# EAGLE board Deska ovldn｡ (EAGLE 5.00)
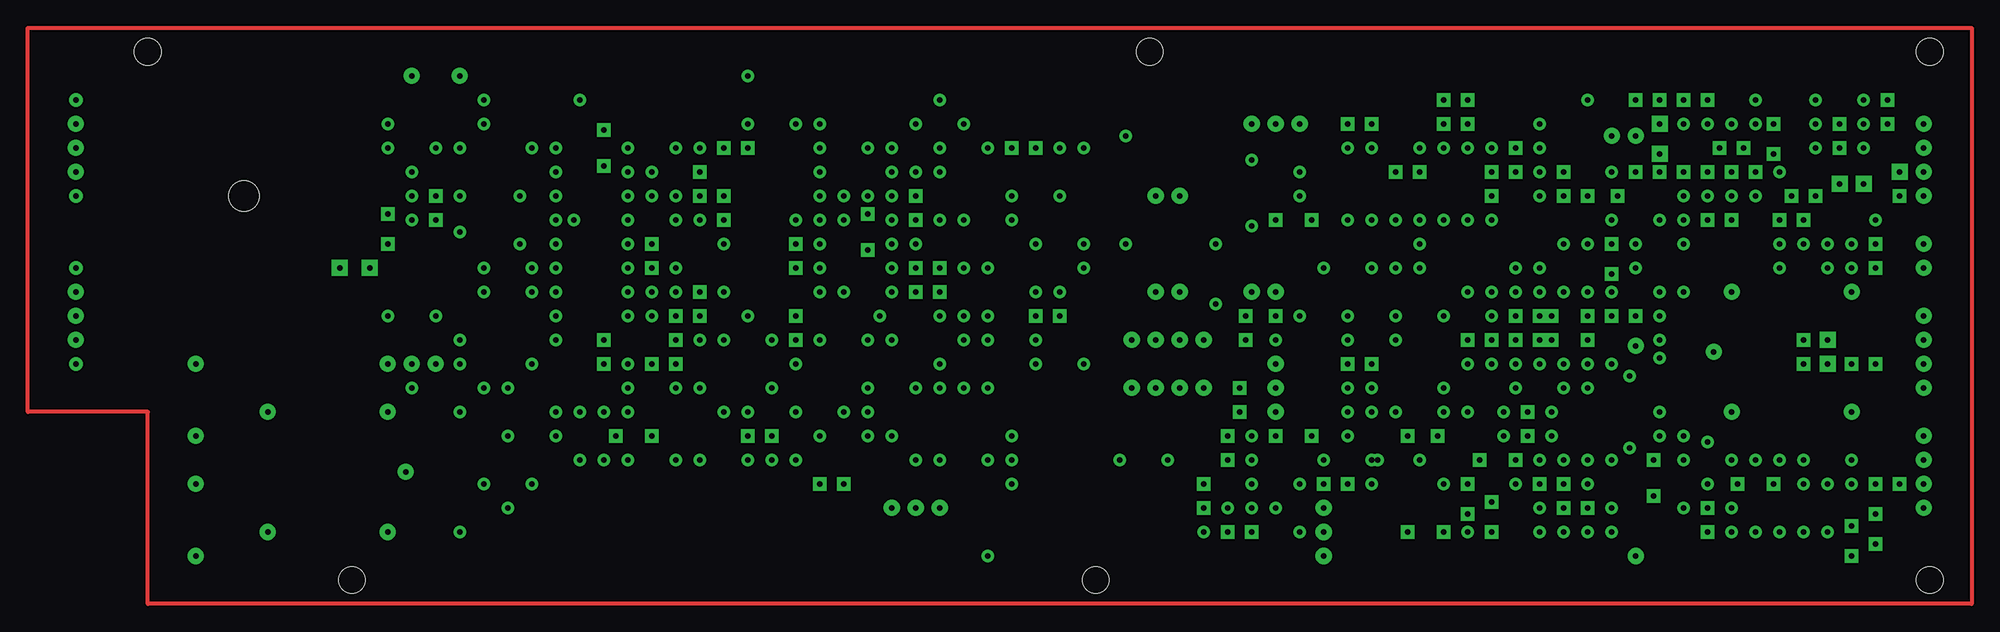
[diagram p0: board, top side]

No outline drawn. Coordinates in mm, seen from the top.
Copper layers (1*16): Top 0.035mm / dielectric 1.5mm / Bottom 0.035mm
Design rules "default": minimum track width 10mil, minimum drill 0.6mm, track to track 8mil, track to pad 8mil, pad to pad 8mil, via to via 8mil, smd to smd 8mil, copper to edge 40mil, drill to drill 8mil, minimum pad ring 10mil, minimum via ring 8mil, stop-mask expansion 4mil, vias tented up to drill 0mil, thermal gap 10mil
Holes 2.8 mm at 98.75,2.5 21.25,2.5 0,57.5 104.38,57.5 185.62,2.5 185.62,57.5
Holes 3.2 mm at 10,42.5

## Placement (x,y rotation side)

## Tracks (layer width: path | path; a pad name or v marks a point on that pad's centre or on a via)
S$1
  Top 0.406: 0,0 0,20 -12.5,20 -12.5,60 190,60 190,0 0,0
S$2  (via drill 0.6 pad 1.68)
  other vias: 5,5
S$3  (via drill 0.6 pad 1.68)
  other vias: 5,12.5
S$4  (via drill 0.6 pad 1.68)
  other vias: 5,17.5
S$5  (via drill 0.6 pad 1.68)
  other vias: 5,25
S$6  (via drill 0.6 pad 1.68)
  other vias: -7.5,50
S$7  (via drill 0.6 pad 1.68)
  other vias: -7.5,45
S$8  (via drill 0.6 pad 1.68)
  other vias: -7.5,27.5
S$9  (via drill 0.6 pad 1.68)
  other vias: -7.5,32.5
S$10  (via drill 0.6 pad 1.68)
  other vias: 12.5,7.5
S$11  (via drill 0.6 pad 1.68)
  other vias: 12.5,20
S$12  (via drill 0.6 pad 1.68)
  other vias: 25,20
S$13  (via drill 0.6 pad 1.68)
  other vias: 25,7.5
S$14  (via drill 0.6 pad 1.68)
  other vias: 26.88,13.75
S$15  (via drill 0.6 pad 1.68)
  other vias: 25,25
S$16  (via drill 0.6 pad 1.27)
  other vias: 25,30
S$17  (via drill 0.6 pad 1.68)
  other vias: 20,35
S$18  (via drill 0.6 pad 1.27)
  other vias: 27.5,40
S$19  (via drill 0.6 pad 1.27)
  other vias: 27.5,42.5
S$20  (via drill 0.6 pad 1.27)
  other vias: 27.5,45
S$21  (via drill 0.6 pad 1.27)
  other vias: 25,47.5
S$22  (via drill 0.6 pad 1.27)
  other vias: 25,50
S$23  (via drill 0.6 pad 1.68)
  other vias: 27.5,55
S$24  (via drill 0.6 pad 1.68)
  other vias: 32.5,55
S$25  (via drill 0.6 pad 1.27)
  other vias: 35,52.5
S$26  (via drill 0.6 pad 1.27)
  other vias: 35,50
S$27  (via drill 0.6 pad 1.27)
  other vias: 32.5,47.5
S$28  (via drill 0.6 pad 1.27)
  other vias: 30,47.5
S$29  (via drill 0.6 pad 1.27)
  other vias: 32.5,42.5
S$30  (via drill 0.6 pad 1.27)
  other vias: 32.5,38.75
S$31  (via drill 0.6 pad 1.27)
  other vias: 38.75,42.5
S$32  (via drill 0.6 pad 1.27)
  other vias: 38.75,37.5
S$33  (via drill 0.6 pad 1.27)
  other vias: 40,47.5
S$34  (via drill 0.6 pad 1.27)
  other vias: 42.5,47.5
S$35  (via drill 0.6 pad 1.27)
  other vias: 42.5,45
S$36  (via drill 0.6 pad 1.27)
  other vias: 42.5,42.5
S$37  (via drill 0.6 pad 1.27)
  other vias: 42.5,40
S$38  (via drill 0.6 pad 1.27)
  other vias: 42.5,37.5
S$39  (via drill 0.6 pad 1.27)
  other vias: 42.5,35
S$40  (via drill 0.6 pad 1.27)
  other vias: 42.5,32.5
S$41  (via drill 0.6 pad 1.27)
  other vias: 42.5,30
S$42  (via drill 0.6 pad 1.27)
  other vias: 42.5,27.5
S$43  (via drill 0.6 pad 1.27)
  other vias: 50,47.5
S$44  (via drill 0.6 pad 1.27)
  other vias: 50,45
S$45  (via drill 0.6 pad 1.27)
  other vias: 50,42.5
S$46  (via drill 0.6 pad 1.27)
  other vias: 50,40
S$47  (via drill 0.6 pad 1.27)
  other vias: 50,37.5
S$48  (via drill 0.6 pad 1.27)
  other vias: 50,35
S$49  (via drill 0.6 pad 1.27)
  other vias: 50,32.5
S$50  (via drill 0.6 pad 1.27)
  other vias: 50,30
S$51  (via drill 0.6 pad 1.27)
  other vias: 55,47.5
S$52  (via drill 0.6 pad 1.27)
  other vias: 57.5,47.5
S$53  (via drill 0.6 pad 1.27)
  other vias: 52.5,45
S$54  (via drill 0.6 pad 1.27)
  other vias: 52.5,42.5
S$55  (via drill 0.6 pad 1.27)
  other vias: 55,42.5
S$56  (via drill 0.6 pad 1.27)
  other vias: 55,40
S$57  (via drill 0.6 pad 1.27)
  other vias: 57.5,40
S$58  (via drill 0.6 pad 1.27)
  other vias: 60,37.5
S$59  (via drill 0.6 pad 1.27)
  other vias: 55,35
S$60  (via drill 0.6 pad 1.27)
  other vias: 55,32.5
S$61  (via drill 0.6 pad 1.27)
  other vias: 52.5,32.5
S$62  (via drill 0.6 pad 1.27)
  other vias: 52.5,30
S$63  (via drill 0.6 pad 1.27)
  other vias: 60,32.5
S$64  (via drill 0.6 pad 1.27)
  other vias: 60,27.5
S$65  (via drill 0.6 pad 1.27)
  other vias: 57.5,27.5
S$66  (via drill 0.6 pad 1.27)
  other vias: 57.5,22.5
S$67  (via drill 0.6 pad 1.27)
  other vias: 55,22.5
S$68  (via drill 0.6 pad 1.27)
  other vias: 50,25
S$69  (via drill 0.6 pad 1.27)
  other vias: 50,22.5
S$70  (via drill 0.6 pad 1.27)
  other vias: 50,20
S$71  (via drill 0.6 pad 1.27)
  other vias: 47.5,20
S$72  (via drill 0.6 pad 1.27)
  other vias: 45,20
S$73  (via drill 0.6 pad 1.27)
  other vias: 42.5,20
S$74  (via drill 0.6 pad 1.27)
  other vias: 42.5,17.5
S$75  (via drill 0.6 pad 1.27)
  other vias: 45,15
S$76  (via drill 0.6 pad 1.27)
  other vias: 47.5,15
S$77  (via drill 0.6 pad 1.27)
  other vias: 50,15
S$78  (via drill 0.6 pad 1.27)
  other vias: 37.5,17.5
S$79  (via drill 0.6 pad 1.27)
  other vias: 37.5,10
S$80  (via drill 0.6 pad 1.27)
  other vias: 40,12.5
S$81  (via drill 0.6 pad 1.27)
  other vias: 35,12.5
S$82  (via drill 0.6 pad 1.27)
  other vias: 32.5,7.5
S$83  (via drill 0.6 pad 1.27)
  other vias: 32.5,20
S$84  (via drill 0.6 pad 1.27)
  other vias: 35,22.5
S$85  (via drill 0.6 pad 1.27)
  other vias: 37.5,22.5
S$86  (via drill 0.6 pad 1.27)
  other vias: 40,25
S$87  (via drill 0.6 pad 1.27)
  other vias: 32.5,25
S$88  (via drill 0.6 pad 1.27)
  other vias: 32.5,27.5
S$89  (via drill 0.6 pad 1.68)
  other vias: 30,25
S$90  (via drill 0.6 pad 1.27)
  other vias: 27.5,22.5
S$91  (via drill 0.6 pad 1.27)
  other vias: 72.5,42.5
S$92  (via drill 0.6 pad 1.27)
  other vias: 30,30
S$93  (via drill 0.6 pad 1.68)
  other vias: 23.12,35
S$94  (via drill 0.6 pad 1.27)
  other vias: 35,35
S$95  (via drill 0.6 pad 1.27)
  other vias: 35,32.5
S$96  (via drill 0.6 pad 1.27)
  other vias: 40,32.5
S$97  (via drill 0.6 pad 1.27)
  other vias: 40,35
S$98  (via drill 0.6 pad 1.27)
  other vias: 45,52.5
S$99  (via drill 0.6 pad 1.27)
  other vias: 62.5,30
S$100  (via drill 0.6 pad 1.27)
  other vias: 65,27.5
S$101  (via drill 0.6 pad 1.27)
  other vias: 67.5,25
S$102  (via drill 0.6 pad 1.27)
  other vias: 70,27.5
S$103  (via drill 0.6 pad 1.27)
  other vias: 70,47.5
S$104  (via drill 0.6 pad 1.27)
  other vias: 70,45
S$105  (via drill 0.6 pad 1.27)
  other vias: 70,42.5
S$106  (via drill 0.6 pad 1.27)
  other vias: 70,40
S$107  (via drill 0.6 pad 1.27)
  other vias: 70,37.5
S$108  (via drill 0.6 pad 1.27)
  other vias: 70,35
S$109  (via drill 0.6 pad 1.27)
  other vias: 70,32.5
S$110  (via drill 0.6 pad 1.27)
  other vias: 72.5,32.5
S$111  (via drill 0.6 pad 1.27)
  other vias: 77.5,32.5
S$112  (via drill 0.6 pad 1.27)
  other vias: 77.5,35
S$113  (via drill 0.6 pad 1.27)
  other vias: 77.5,37.5
S$114  (via drill 0.6 pad 1.27)
  other vias: 77.5,40
S$115  (via drill 0.6 pad 1.27)
  other vias: 77.5,42.5
S$116  (via drill 0.6 pad 1.27)
  other vias: 77.5,45
S$117  (via drill 0.6 pad 1.27)
  other vias: 77.5,47.5
S$118  (via drill 0.6 pad 1.27)
  other vias: 80,50
S$119  (via drill 0.6 pad 1.27)
  other vias: 80,45
S$120  (via drill 0.6 pad 1.27)
  other vias: 82.5,45
S$121  (via drill 0.6 pad 1.27)
  other vias: 82.5,47.5
S$122  (via drill 0.6 pad 1.27)
  other vias: 82.5,40
S$123  (via drill 0.6 pad 1.27)
  other vias: 82.5,52.5
S$124  (via drill 0.6 pad 1.27)
  other vias: 85,50
S$125  (via drill 0.6 pad 1.27)
  other vias: 85,40
S$126  (via drill 0.6 pad 1.27)
  other vias: 80,37.5
S$127  (via drill 0.6 pad 1.27)
  other vias: 85,35
S$128  (via drill 0.6 pad 1.27)
  other vias: 87.5,35
S$129  (via drill 0.6 pad 1.27)
  other vias: 85,30
S$130  (via drill 0.6 pad 1.27)
  other vias: 87.5,30
S$131  (via drill 0.6 pad 1.27)
  other vias: 85,27.5
S$132  (via drill 0.6 pad 1.27)
  other vias: 87.5,27.5
S$133  (via drill 0.6 pad 1.27)
  other vias: 65,22.5
S$134  (via drill 0.6 pad 1.27)
  other vias: 62.5,20
S$135  (via drill 0.6 pad 1.27)
  other vias: 62.5,15
S$136  (via drill 0.6 pad 1.27)
  other vias: 65,15
S$137  (via drill 0.6 pad 1.27)
  other vias: 67.5,15
S$138  (via drill 0.6 pad 1.27)
  other vias: 67.5,20
S$139  (via drill 0.6 pad 1.27)
  other vias: 70,17.5
S$140  (via drill 0.6 pad 1.27)
  other vias: 72.5,20
S$141  (via drill 0.6 pad 1.27)
  other vias: 60,20
S$142  (via drill 0.6 pad 1.27)
  other vias: 57.5,15
S$143  (via drill 0.6 pad 1.27)
  other vias: 55,15
S$144  (via drill 0.6 pad 1.27)
  other vias: 75,27.5
S$145  (via drill 0.6 pad 1.27)
  other vias: 76.25,30
S$146  (via drill 0.6 pad 1.27)
  other vias: 67.5,40
S$147  (via drill 0.6 pad 1.27)
  other vias: 70,50
S$148  (via drill 0.6 pad 1.27)
  other vias: 67.5,50
S$149  (via drill 0.6 pad 1.27)
  other vias: 62.5,50
S$150  (via drill 0.6 pad 1.27)
  other vias: 62.5,55
S$151  (via drill 0.6 pad 1.42)
  other vias: 30,42.5
S$152  (via drill 0.6 pad 1.42)
  other vias: 30,40
S$153  (via drill 0.6 pad 1.42)
  other vias: 25,40.62
S$154  (via drill 0.6 pad 1.42)
  other vias: 25,37.5
S$155  (via drill 0.6 pad 1.42)
  other vias: 47.5,45.62
S$156  (via drill 0.6 pad 1.42)
  other vias: 47.5,49.38
S$157  (via drill 0.6 pad 1.42)
  other vias: 47.5,27.5
S$158  (via drill 0.6 pad 1.42)
  other vias: 47.5,25
S$159  (via drill 0.6 pad 1.42)
  other vias: 52.5,25
S$160  (via drill 0.6 pad 1.42)
  other vias: 55,25
S$161  (via drill 0.6 pad 1.42)
  other vias: 55,27.5
S$162  (via drill 0.6 pad 1.42)
  other vias: 55,30
S$163  (via drill 0.6 pad 1.42)
  other vias: 57.5,30
S$164  (via drill 0.6 pad 1.42)
  other vias: 57.5,32.5
S$165  (via drill 0.6 pad 1.42)
  other vias: 52.5,35
S$166  (via drill 0.6 pad 1.42)
  other vias: 52.5,37.5
S$167  (via drill 0.6 pad 1.42)
  other vias: 60,47.5
S$168  (via drill 0.6 pad 1.42)
  other vias: 62.5,47.5
S$169  (via drill 0.6 pad 1.42)
  other vias: 57.5,45
S$170  (via drill 0.6 pad 1.42)
  other vias: 57.5,42.5
S$171  (via drill 0.6 pad 1.42)
  other vias: 60,42.5
S$172  (via drill 0.6 pad 1.42)
  other vias: 60,40
S$173  (via drill 0.6 pad 1.42)
  other vias: 67.5,37.5
S$174  (via drill 0.6 pad 1.42)
  other vias: 67.5,35
S$175  (via drill 0.6 pad 1.42)
  other vias: 67.5,30
S$176  (via drill 0.6 pad 1.42)
  other vias: 67.5,27.5
S$177  (via drill 0.6 pad 1.42)
  other vias: 62.5,17.5
S$178  (via drill 0.6 pad 1.42)
  other vias: 65,17.5
S$179  (via drill 0.6 pad 1.42)
  other vias: 70,12.5
S$180  (via drill 0.6 pad 1.42)
  other vias: 72.5,12.5
S$181  (via drill 0.6 pad 1.42)
  other vias: 52.5,17.5
S$182  (via drill 0.6 pad 1.42)
  other vias: 48.75,17.5
S$183  (via drill 0.6 pad 1.42)
  other vias: 80,42.5
S$184  (via drill 0.6 pad 1.42)
  other vias: 80,40
S$185  (via drill 0.6 pad 1.42)
  other vias: 80,35
S$186  (via drill 0.6 pad 1.42)
  other vias: 80,32.5
S$187  (via drill 0.6 pad 1.42)
  other vias: 82.5,32.5
S$188  (via drill 0.6 pad 1.42)
  other vias: 82.5,35
S$189  (via drill 0.6 pad 1.42)
  other vias: -7.5,52.5
S$190  (via drill 0.6 pad 1.42)
  other vias: -7.5,42.5
S$191  (via drill 0.6 pad 1.42)
  other vias: -7.5,35
S$192  (via drill 0.6 pad 1.42)
  other vias: -7.5,25
S$193  (via drill 0.6 pad 1.27)
  other vias: 75,22.5
S$194  (via drill 0.6 pad 1.27)
  other vias: 75,20
S$195  (via drill 0.6 pad 1.27)
  other vias: 75,17.5
S$196  (via drill 0.6 pad 1.27)
  other vias: 77.5,17.5
S$197  (via drill 0.6 pad 1.27)
  other vias: 80,22.5
S$198  (via drill 0.6 pad 1.27)
  other vias: 82.5,22.5
S$199  (via drill 0.6 pad 1.27)
  other vias: 82.5,15
S$200  (via drill 0.6 pad 1.27)
  other vias: 80,15
S$201  (via drill 0.6 pad 1.68)
  other vias: 80,10 77.5,10
S$202  (via drill 0.6 pad 1.68)
  other vias: 82.5,10
S$203  (via drill 0.6 pad 1.27)
  other vias: 85,22.5
S$204  (via drill 0.6 pad 1.27)
  other vias: 87.5,22.5
S$205  (via drill 0.6 pad 1.27)
  other vias: 44.38,40
S$206  (via drill 0.6 pad 1.27)
  other vias: 72.5,40
S$207  (via drill 0.6 pad 1.27)
  other vias: 75,42.5
S$208  (via drill 0.6 pad 1.27)
  other vias: 75,47.5
S$209  (via drill 0.6 pad 1.27)
  other vias: 77.5,27.5
S$210  (via drill 0.6 pad 1.27)
  other vias: 82.5,30
S$211  (via drill 0.6 pad 1.27)
  other vias: 82.5,25
S$212  (via drill 0.6 pad 1.27)
  other vias: 90,40
S$213  (via drill 0.6 pad 1.27)
  other vias: 90,42.5
S$214  (via drill 0.6 pad 1.27)
  other vias: 92.5,37.5
S$215  (via drill 0.6 pad 1.27)
  other vias: 92.5,32.5
S$216  (via drill 0.6 pad 1.27)
  other vias: 92.5,27.5
S$217  (via drill 0.6 pad 1.27)
  other vias: 92.5,25
S$218  (via drill 0.6 pad 1.27)
  other vias: 97.5,25
S$219  (via drill 0.6 pad 1.27)
  other vias: 87.5,15
S$220  (via drill 0.6 pad 1.27)
  other vias: 90,17.5
S$221  (via drill 0.6 pad 1.27)
  other vias: 90,15
S$222  (via drill 0.6 pad 1.27)
  other vias: 90,12.5
S$223  (via drill 0.6 pad 1.27)
  other vias: 87.5,5
S$224  (via drill 0.6 pad 1.27)
  other vias: 87.5,47.5
S$225  (via drill 0.6 pad 1.27)
  other vias: 95,47.5
S$226  (via drill 0.6 pad 1.27)
  other vias: 97.5,47.5
S$227  (via drill 0.6 pad 1.27)
  other vias: 101.88,48.75
S$228  (via drill 0.6 pad 1.27)
  other vias: 97.5,37.5
S$229  (via drill 0.6 pad 1.27)
  other vias: 97.5,35
S$230  (via drill 0.6 pad 1.27)
  other vias: 95,32.5
S$231  (via drill 0.6 pad 1.27)
  other vias: 95,42.5
S$232  (via drill 0.6 pad 1.27)
  other vias: 101.88,37.5
S$233  (via drill 0.6 pad 1.27)
  other vias: 111.25,37.5
S$234  (via drill 0.6 pad 1.68)
  other vias: 105,42.5
S$235  (via drill 0.6 pad 1.68)
  other vias: 107.5,42.5
S$236  (via drill 0.6 pad 1.68)
  other vias: 107.5,32.5
S$237  (via drill 0.6 pad 1.68)
  other vias: 105,32.5
S$238  (via drill 0.6 pad 1.68)
  other vias: 102.5,27.5
S$239  (via drill 0.6 pad 1.68)
  other vias: -7.5,47.5
S$240  (via drill 0.6 pad 1.68)
  other vias: -7.5,30
S$241  (via drill 0.6 pad 1.68)
  other vias: 105,27.5
S$242  (via drill 0.6 pad 1.68)
  other vias: 107.5,27.5
S$243  (via drill 0.6 pad 1.68)
  other vias: 110,27.5
S$244  (via drill 0.6 pad 1.68)
  other vias: 110,22.5
S$245  (via drill 0.6 pad 1.68)
  other vias: 102.5,22.5
S$246  (via drill 0.6 pad 1.68)
  other vias: 105,22.5
S$247  (via drill 0.6 pad 1.68)
  other vias: 107.5,22.5
S$248  (via drill 0.6 pad 1.27)
  other vias: 106.25,15
S$249  (via drill 0.6 pad 1.27)
  other vias: 101.25,15
S$250  (via drill 0.6 pad 1.68)
  other vias: 115,50
S$251  (via drill 0.6 pad 1.68)
  other vias: 120,50
S$252  (via drill 0.6 pad 1.68)
  other vias: 117.5,50
S$253  (via drill 0.6 pad 1.27)
  other vias: 115,46.25
S$254  (via drill 0.6 pad 1.27)
  other vias: 115,39.38
S$255  (via drill 0.6 pad 1.27)
  other vias: 120,45
S$256  (via drill 0.6 pad 1.27)
  other vias: 120,42.5
S$257  (via drill 0.6 pad 1.27)
  other vias: 125,47.5
S$258  (via drill 0.6 pad 1.27)
  other vias: 127.5,47.5
S$259  (via drill 0.6 pad 1.27)
  other vias: 125,40
S$260  (via drill 0.6 pad 1.27)
  other vias: 127.5,40
S$261  (via drill 0.6 pad 1.27)
  other vias: 130,40
S$262  (via drill 0.6 pad 1.27)
  other vias: 132.5,40
S$263  (via drill 0.6 pad 1.27)
  other vias: 135,40
S$264  (via drill 0.6 pad 1.27)
  other vias: 137.5,40
S$265  (via drill 0.6 pad 1.27)
  other vias: 140,40
S$266  (via drill 0.6 pad 1.27)
  other vias: 140,47.5
S$267  (via drill 0.6 pad 1.27)
  other vias: 137.5,47.5
S$268  (via drill 0.6 pad 1.27)
  other vias: 135,47.5
S$269  (via drill 0.6 pad 1.27)
  other vias: 132.5,47.5
S$270  (via drill 0.6 pad 1.27)
  other vias: 145,47.5
S$271  (via drill 0.6 pad 1.27)
  other vias: 145,50
S$272  (via drill 0.6 pad 1.27)
  other vias: 145,45
S$273  (via drill 0.6 pad 1.27)
  other vias: 145,42.5
S$274  (via drill 0.6 pad 1.27)
  other vias: 132.5,37.5
S$275  (via drill 0.6 pad 1.27)
  other vias: 147.5,37.5
S$276  (via drill 0.6 pad 1.27)
  other vias: 132.5,35
S$277  (via drill 0.6 pad 1.27)
  other vias: 130,35
S$278  (via drill 0.6 pad 1.27)
  other vias: 127.5,35
S$279  (via drill 0.6 pad 1.27)
  other vias: 122.5,35
S$280  (via drill 0.6 pad 1.68)
  other vias: 115,32.5
S$281  (via drill 0.6 pad 1.68)
  other vias: 117.5,32.5
S$282  (via drill 0.6 pad 1.27)
  other vias: 117.5,27.5
S$283  (via drill 0.6 pad 1.27)
  other vias: 120,30
S$284  (via drill 0.6 pad 1.27)
  other vias: 125,30
S$285  (via drill 0.6 pad 1.27)
  other vias: 125,27.5
S$286  (via drill 0.6 pad 1.27)
  other vias: 130,30
S$287  (via drill 0.6 pad 1.27)
  other vias: 130,27.5
S$288  (via drill 0.6 pad 1.27)
  other vias: 125,22.5
S$289  (via drill 0.6 pad 1.27)
  other vias: 127.5,22.5
S$290  (via drill 0.6 pad 1.27)
  other vias: 127.5,20
S$291  (via drill 0.6 pad 1.27)
  other vias: 125,20
S$292  (via drill 0.6 pad 1.27)
  other vias: 130,20
S$293  (via drill 0.6 pad 1.27)
  other vias: 125,17.5
S$294  (via drill 0.6 pad 1.27)
  other vias: 127.5,15
S$295  (via drill 0.6 pad 1.27)
  other vias: 122.5,15
S$296  (via drill 0.6 pad 1.27)
  other vias: 120,12.5
S$297  (via drill 0.6 pad 1.27)
  other vias: 127.5,12.5
S$298  (via drill 0.6 pad 1.68)
  other vias: 122.5,10
S$299  (via drill 0.6 pad 1.68)
  other vias: 122.5,7.5
S$300  (via drill 0.6 pad 1.68)
  other vias: 122.5,5
S$301  (via drill 0.6 pad 1.68)
  other vias: 117.5,25
S$302  (via drill 0.6 pad 1.68)
  other vias: 117.5,22.5
S$303  (via drill 0.6 pad 1.68)
  other vias: 117.5,20
S$304  (via drill 0.6 pad 1.27)
  other vias: 115,17.5
S$305  (via drill 0.6 pad 1.27)
  other vias: 115,15
S$306  (via drill 0.6 pad 1.27)
  other vias: 115,12.5
S$307  (via drill 0.6 pad 1.27)
  other vias: 115,10
S$308  (via drill 0.6 pad 1.27)
  other vias: 117.5,10
S$309  (via drill 0.6 pad 1.27)
  other vias: 112.5,10
S$310  (via drill 0.6 pad 1.27)
  other vias: 110,7.5
S$311  (via drill 0.6 pad 1.27)
  other vias: 128.12,15
S$312  (via drill 0.6 pad 1.27)
  other vias: 132.5,15
S$313  (via drill 0.6 pad 1.27)
  other vias: 135,12.5 135,12.5
S$314  (via drill 0.6 pad 1.27)
  other vias: 135,20
S$315  (via drill 0.6 pad 1.27)
  other vias: 137.5,20
S$316  (via drill 0.6 pad 1.27)
  other vias: 135,22.5
S$317  (via drill 0.6 pad 1.27)
  other vias: 137.5,7.5
S$318  (via drill 0.6 pad 1.27)
  other vias: 145,7.5
S$319  (via drill 0.6 pad 1.27)
  other vias: 147.5,7.5
S$320  (via drill 0.6 pad 1.27)
  other vias: 150,7.5
S$321  (via drill 0.6 pad 1.27)
  other vias: 152.5,7.5
S$322  (via drill 0.6 pad 1.42)
  other vias: 90,47.5
S$323  (via drill 0.6 pad 1.42)
  other vias: 92.5,47.5
S$324  (via drill 0.6 pad 1.42)
  other vias: 92.5,30
S$325  (via drill 0.6 pad 1.42)
  other vias: 95,30
S$326  (via drill 0.6 pad 1.42)
  other vias: 117.5,40
S$327  (via drill 0.6 pad 1.42)
  other vias: 121.25,40
S$328  (via drill 0.6 pad 1.42)
  other vias: 125,50
S$329  (via drill 0.6 pad 1.42)
  other vias: 127.5,50
S$330  (via drill 0.6 pad 1.42)
  other vias: 135,50
S$331  (via drill 0.6 pad 1.42)
  other vias: 135,52.5
S$332  (via drill 0.6 pad 1.42)
  other vias: 137.5,52.5
S$333  (via drill 0.6 pad 1.42)
  other vias: 137.5,50
S$334  (via drill 0.6 pad 1.42)
  other vias: 142.5,47.5
S$335  (via drill 0.6 pad 1.42)
  other vias: 142.5,45
S$336  (via drill 0.6 pad 1.42)
  other vias: 140,45
S$337  (via drill 0.6 pad 1.42)
  other vias: 140,42.5
S$338  (via drill 0.6 pad 1.42)
  other vias: 147.5,45
S$339  (via drill 0.6 pad 1.42)
  other vias: 147.5,42.5
S$340  (via drill 0.6 pad 1.42)
  other vias: 132.5,45
S$341  (via drill 0.6 pad 1.42)
  other vias: 130,45
S$342  (via drill 0.6 pad 1.27)
  other vias: 111.25,31.25
S$343  (via drill 0.6 pad 1.42)
  other vias: 114.38,30
S$344  (via drill 0.6 pad 1.42)
  other vias: 117.5,30
S$345  (via drill 0.6 pad 1.42)
  other vias: 125,25
S$346  (via drill 0.6 pad 1.42)
  other vias: 127.5,25
S$347  (via drill 0.6 pad 1.42)
  other vias: 122.5,12.5
S$348  (via drill 0.6 pad 1.42)
  other vias: 125,12.5
S$349  (via drill 0.6 pad 1.42)
  other vias: 115,7.5
S$350  (via drill 0.6 pad 1.42)
  other vias: 112.5,7.5
S$351  (via drill 0.6 pad 1.42)
  other vias: 110,10
S$352  (via drill 0.6 pad 1.42)
  other vias: 110,12.5
S$353  (via drill 0.6 pad 1.42)
  other vias: 112.5,15
S$354  (via drill 0.6 pad 1.42)
  other vias: 112.5,17.5
S$355  (via drill 0.6 pad 1.42)
  other vias: 137.5,9.38 131.25,7.5 135,7.5
S$356  (via drill 0.6 pad 1.42)
  other vias: 137.5,12.5
S$357  (via drill 0.6 pad 1.42)
  other vias: 113.75,20
S$358  (via drill 0.6 pad 1.42)
  other vias: 113.75,22.5
S$359  (via drill 0.6 pad 1.27)
  other vias: 120,7.5
S$360  (via drill 0.6 pad 1.27)
  other vias: 152.5,15
S$361  (via drill 0.6 pad 1.27)
  other vias: 150,15
S$362  (via drill 0.6 pad 1.27)
  other vias: 147.5,15
S$363  (via drill 0.6 pad 1.27)
  other vias: 145,15
S$364  (via drill 0.6 pad 1.27)
  other vias: 150,12.5
S$365  (via drill 0.6 pad 1.27)
  other vias: 142.5,12.5
S$366  (via drill 0.6 pad 1.27)
  other vias: 145,10
S$367  (via drill 0.6 pad 1.27)
  other vias: 152.5,10
S$368  (via drill 0.6 pad 1.27)
  other vias: 160,10
S$369  (via drill 0.6 pad 1.27)
  other vias: 160,15
S$370  (via drill 0.6 pad 1.27)
  other vias: 154.38,16.25
S$371  (via drill 0.6 pad 1.27)
  other vias: 157.5,17.5
S$372  (via drill 0.6 pad 1.27)
  other vias: 157.5,20
S$373  (via drill 0.6 pad 1.68)
  other vias: 165,20
S$374  (via drill 0.6 pad 1.68)
  other vias: 177.5,20
S$375  (via drill 0.6 pad 1.68)
  other vias: 165,32.5
S$376  (via drill 0.6 pad 1.68)
  other vias: 177.5,32.5
S$377  (via drill 0.6 pad 1.68)
  other vias: 163.12,26.25
S$378  (via drill 0.6 pad 1.68)
  other vias: 185,50
S$379  (via drill 0.6 pad 1.68)
  other vias: 185,47.5
S$380  (via drill 0.6 pad 1.68)
  other vias: 185,45
S$381  (via drill 0.6 pad 1.68)
  other vias: 185,42.5
S$382  (via drill 0.6 pad 1.68)
  other vias: 185,37.5
S$383  (via drill 0.6 pad 1.68)
  other vias: 185,35
S$384  (via drill 0.6 pad 1.68)
  other vias: 185,30
S$385  (via drill 0.6 pad 1.68)
  other vias: 185,27.5
S$386  (via drill 0.6 pad 1.68)
  other vias: 185,25
S$387  (via drill 0.6 pad 1.68)
  other vias: 185,22.5
S$388  (via drill 0.6 pad 1.68)
  other vias: 185,17.5
S$389  (via drill 0.6 pad 1.68)
  other vias: 185,15
S$390  (via drill 0.6 pad 1.68)
  other vias: 185,12.5
S$391  (via drill 0.6 pad 1.68)
  other vias: 185,10
S$392  (via drill 0.6 pad 1.27)
  other vias: 173.75,52.5
S$393  (via drill 0.6 pad 1.27)
  other vias: 178.75,52.5
S$394  (via drill 0.6 pad 1.27)
  other vias: 173.75,50
S$395  (via drill 0.6 pad 1.27)
  other vias: 173.75,47.5
S$396  (via drill 0.6 pad 1.27)
  other vias: 178.75,50
S$397  (via drill 0.6 pad 1.27)
  other vias: 178.75,47.5
S$398  (via drill 0.6 pad 1.27)
  other vias: 180,40
S$399  (via drill 0.6 pad 1.27)
  other vias: 177.5,37.5
S$400  (via drill 0.6 pad 1.27)
  other vias: 177.5,35
S$401  (via drill 0.6 pad 1.27)
  other vias: 175,35
S$402  (via drill 0.6 pad 1.27)
  other vias: 175,37.5
S$403  (via drill 0.6 pad 1.27)
  other vias: 172.5,37.5
S$404  (via drill 0.6 pad 1.27)
  other vias: 170,37.5
S$405  (via drill 0.6 pad 1.27)
  other vias: 170,35
S$406  (via drill 0.6 pad 1.27)
  other vias: 167.5,50
S$407  (via drill 0.6 pad 1.27)
  other vias: 165,50
S$408  (via drill 0.6 pad 1.27)
  other vias: 162.5,50
S$409  (via drill 0.6 pad 1.27)
  other vias: 160,50
S$410  (via drill 0.6 pad 1.27)
  other vias: 160,42.5
S$411  (via drill 0.6 pad 1.27)
  other vias: 162.5,42.5
S$412  (via drill 0.6 pad 1.27)
  other vias: 165,42.5
S$413  (via drill 0.6 pad 1.27)
  other vias: 167.5,42.5
S$414  (via drill 0.6 pad 1.27)
  other vias: 167.5,52.5
S$415  (via drill 0.6 pad 1.68)
  other vias: 152.5,48.75
S$416  (via drill 0.6 pad 1.68)
  other vias: 155,48.75
S$417  (via drill 0.6 pad 1.27)
  other vias: 150,52.5
S$418  (via drill 0.6 pad 1.27)
  other vias: 152.5,45
S$419  (via drill 0.6 pad 1.27)
  other vias: 152.5,40
S$420  (via drill 0.6 pad 1.27)
  other vias: 157.5,40
S$421  (via drill 0.6 pad 1.27)
  other vias: 155,37.5
S$422  (via drill 0.6 pad 1.27)
  other vias: 160,40
S$423  (via drill 0.6 pad 1.27)
  other vias: 160,37.5
S$424  (via drill 0.6 pad 1.27)
  other vias: 150,37.5
S$425  (via drill 0.6 pad 1.27)
  other vias: 155,35
S$426  (via drill 0.6 pad 1.27)
  other vias: 150,32.5
S$427  (via drill 0.6 pad 1.27)
  other vias: 152.5,32.5
S$428  (via drill 0.6 pad 1.27)
  other vias: 147.5,32.5
S$429  (via drill 0.6 pad 1.27)
  other vias: 145,32.5
S$430  (via drill 0.6 pad 1.27)
  other vias: 142.5,32.5
S$431  (via drill 0.6 pad 1.27)
  other vias: 140,32.5
S$432  (via drill 0.6 pad 1.27)
  other vias: 137.5,32.5
S$433  (via drill 0.6 pad 1.27)
  other vias: 137.5,25
S$434  (via drill 0.6 pad 1.27)
  other vias: 140,25
S$435  (via drill 0.6 pad 1.27)
  other vias: 142.5,25
S$436  (via drill 0.6 pad 1.27)
  other vias: 145,25
S$437  (via drill 0.6 pad 1.27)
  other vias: 147.5,25
S$438  (via drill 0.6 pad 1.27)
  other vias: 150,25
S$439  (via drill 0.6 pad 1.27)
  other vias: 152.5,25
S$440  (via drill 0.6 pad 1.27)
  other vias: 142.5,22.5
S$441  (via drill 0.6 pad 1.27)
  other vias: 147.5,22.5
S$442  (via drill 0.6 pad 1.27)
  other vias: 150,22.5
S$443  (via drill 0.6 pad 1.27)
  other vias: 154.38,23.75
S$444  (via drill 0.6 pad 1.27)
  other vias: 157.5,25.62
S$445  (via drill 0.6 pad 1.27)
  other vias: 157.5,27.5
S$446  (via drill 0.6 pad 1.27)
  other vias: 157.5,30
S$447  (via drill 0.6 pad 1.27)
  other vias: 157.5,32.5
S$448  (via drill 0.6 pad 1.27)
  other vias: 160,32.5
S$449  (via drill 0.6 pad 1.27)
  other vias: 160,17.5
S$450  (via drill 0.6 pad 1.27)
  other vias: 162.5,16.88
S$451  (via drill 0.6 pad 1.27)
  other vias: 165,15
S$452  (via drill 0.6 pad 1.27)
  other vias: 167.5,15
S$453  (via drill 0.6 pad 1.27)
  other vias: 170,15
S$454  (via drill 0.6 pad 1.27)
  other vias: 172.5,15
S$455  (via drill 0.6 pad 1.27)
  other vias: 165,7.5
S$456  (via drill 0.6 pad 1.27)
  other vias: 167.5,7.5
S$457  (via drill 0.6 pad 1.27)
  other vias: 170,7.5
S$458  (via drill 0.6 pad 1.27)
  other vias: 172.5,7.5
S$459  (via drill 0.6 pad 1.27)
  other vias: 175,7.5
S$460  (via drill 0.6 pad 1.27)
  other vias: 175,12.5
S$461  (via drill 0.6 pad 1.27)
  other vias: 177.5,12.5
S$462  (via drill 0.6 pad 1.27)
  other vias: 177.5,15
S$463  (via drill 0.6 pad 1.27)
  other vias: 172.5,12.5
S$464  (via drill 0.6 pad 1.27)
  other vias: 165,10
S$465  (via drill 0.6 pad 1.27)
  other vias: 140,30
S$466  (via drill 0.6 pad 1.27)
  other vias: 135,30
S$467  (via drill 0.6 pad 1.27)
  other vias: 141.25,20
S$468  (via drill 0.6 pad 1.27)
  other vias: 141.25,17.5
S$469  (via drill 0.6 pad 1.27)
  other vias: 146.25,20
S$470  (via drill 0.6 pad 1.27)
  other vias: 146.25,17.5
S$471  (via drill 0.6 pad 1.42)
  other vias: 162.5,52.5
S$472  (via drill 0.6 pad 1.42)
  other vias: 160,52.5
S$473  (via drill 0.6 pad 1.42)
  other vias: 157.5,52.5
S$474  (via drill 0.6 pad 1.42)
  other vias: 155,52.5
S$475  (via drill 0.6 pad 1.42)
  other vias: 166.25,47.5
S$476  (via drill 0.6 pad 1.42)
  other vias: 163.75,47.5
S$477  (via drill 0.6 pad 1.42)
  other vias: 167.5,45
S$478  (via drill 0.6 pad 1.42)
  other vias: 165,45
S$479  (via drill 0.6 pad 1.42)
  other vias: 162.5,45
S$480  (via drill 0.6 pad 1.42)
  other vias: 160,45
S$481  (via drill 0.6 pad 1.42)
  other vias: 157.5,45
S$482  (via drill 0.6 pad 1.42)
  other vias: 155,45
S$483  (via drill 0.6 pad 1.42)
  other vias: 170,40
S$484  (via drill 0.6 pad 1.42)
  other vias: 172.5,40
S$485  (via drill 0.6 pad 1.42)
  other vias: 171.25,42.5
S$486  (via drill 0.6 pad 1.42)
  other vias: 173.75,42.5
S$487  (via drill 0.6 pad 1.42)
  other vias: 180,35
S$488  (via drill 0.6 pad 1.42)
  other vias: 180,37.5
S$489  (via drill 0.6 pad 1.42)
  other vias: 176.25,50
S$490  (via drill 0.6 pad 1.42)
  other vias: 177.5,5
S$491  (via drill 0.6 pad 1.42)
  other vias: 181.25,52.5
S$492  (via drill 0.6 pad 1.42)
  other vias: 176.25,47.5
S$493  (via drill 0.6 pad 1.42)
  other vias: 180,25
S$494  (via drill 0.6 pad 1.42)
  other vias: 177.5,25
S$495  (via drill 0.6 pad 1.42)
  other vias: 172.5,25
S$496  (via drill 0.6 pad 1.42)
  other vias: 172.5,27.5
S$497  (via drill 0.6 pad 1.42)
  other vias: 182.5,12.5
S$498  (via drill 0.6 pad 1.42)
  other vias: 180,12.5
S$499  (via drill 0.6 pad 1.42)
  other vias: 177.5,8.12
S$500  (via drill 0.6 pad 1.42)
  other vias: 180,9.38
S$501  (via drill 0.6 pad 1.42)
  other vias: 180,6.25
S$502  (via drill 0.6 pad 1.42)
  other vias: 131.25,17.5
S$503  (via drill 0.6 pad 1.42)
  other vias: 169.38,12.5
S$504  (via drill 0.6 pad 1.42)
  other vias: 165.62,12.5
S$505  (via drill 0.6 pad 1.42)
  other vias: 162.5,7.5
S$506  (via drill 0.6 pad 1.42)
  other vias: 162.5,10
S$507  (via drill 0.6 pad 1.42)
  other vias: 150,10
S$508  (via drill 0.6 pad 1.42)
  other vias: 147.5,10
S$509  (via drill 0.6 pad 1.42)
  other vias: 147.5,12.5
S$510  (via drill 0.6 pad 1.42)
  other vias: 145,12.5
S$511  (via drill 0.6 pad 1.42)
  other vias: 142.5,15
S$512  (via drill 0.6 pad 1.42)
  other vias: 138.75,15
S$513  (via drill 0.6 pad 1.68)
  other vias: 155,5
S$514  (via drill 0.6 pad 1.42)
  other vias: 140,7.5
S$515  (via drill 0.6 pad 1.42)
  other vias: 140,10.62
S$516  (via drill 0.6 pad 1.42)
  other vias: 181.25,50
S$517  (via drill 0.6 pad 1.42)
  other vias: 143.75,20
S$518  (via drill 0.6 pad 1.42)
  other vias: 143.75,17.5
S$519  (via drill 0.6 pad 1.42)
  other vias: 137.5,27.5
S$520  (via drill 0.6 pad 1.42)
  other vias: 140,27.5
S$521  (via drill 0.6 pad 1.42)
  other vias: 142.5,27.5
S$522  (via drill 0.6 pad 1.42)
  other vias: 142.5,30
S$523  (via drill 0.6 pad 1.42)
  other vias: 145,30
S$524  (via drill 0.6 pad 1.42)
  other vias: 146.25,30 150,30
S$525  (via drill 0.6 pad 1.68)
  other vias: 155,26.88
S$526  (via drill 0.6 pad 1.42)
  other vias: 152.5,30
S$527  (via drill 0.6 pad 1.42)
  other vias: 155,30
S$528  (via drill 0.6 pad 1.42)
  other vias: 145,27.5
S$529  (via drill 0.6 pad 1.42)
  other vias: 146.25,27.5
S$530  (via drill 0.6 pad 1.42)
  other vias: 150,27.5
S$531  (via drill 0.6 pad 1.42)
  other vias: 165,40
S$532  (via drill 0.6 pad 1.42)
  other vias: 162.5,40
S$533  (via drill 0.6 pad 1.27)
  other vias: 170,45
S$534  (via drill 0.6 pad 1.27)
  other vias: 162.5,12.5
S$535  (via drill 0.6 pad 1.27)
  other vias: 142.5,35
S$536  (via drill 0.6 pad 1.27)
  other vias: 145,35
S$537  (via drill 0.6 pad 1.68)
  other vias: 27.5,25
S$538  (via drill 0.6 pad 1.42)
  other vias: 134.38,17.5
S$539  (via drill 0.6 pad 1.42)
  other vias: 150,42.5
S$540  (via drill 0.6 pad 1.42)
  other vias: 153.12,42.5
S$541  (via drill 0.6 pad 1.42)
  other vias: 182.5,42.5
S$542  (via drill 0.6 pad 1.68)
  other vias: 175,25
S$543  (via drill 0.6 pad 1.42)
  other vias: 152.5,37.5
S$544  (via drill 0.6 pad 1.42)
  other vias: 152.5,34.38
S$545  (via drill 0.6 pad 1.42)
  other vias: 169.38,46.88
S$546  (via drill 0.6 pad 1.42)
  other vias: 169.38,50
S$547  (via drill 0.6 pad 1.42)
  other vias: 156.88,15
S$548  (via drill 0.6 pad 1.42)
  other vias: 156.88,11.25
S$549  (via drill 0.6 pad 1.42)
  other vias: 114.38,27.5
S$550  (via drill 0.6 pad 1.42)
  other vias: 117.5,17.5
S$551  (via drill 0.6 pad 1.42)
  other vias: 121.25,17.5
S$552  (via drill 0.6 pad 1.42)
  other vias: 75,40.62
S$553  (via drill 0.6 pad 1.42)
  other vias: 75,36.88
S$554  (via drill 0.6 pad 1.68)
  other vias: 176.25,43.75
S$555  (via drill 0.6 pad 1.68)
  other vias: 178.75,43.75
S$556  (via drill 0.6 pad 1.68)
  other vias: 182.5,45
S$557  (via drill 0.6 pad 1.68)
  other vias: 175,27.5
S$558  (via drill 0.6 pad 1.68)
  other vias: 157.5,50
S$559  (via drill 0.6 pad 1.68)
  other vias: 157.5,46.88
